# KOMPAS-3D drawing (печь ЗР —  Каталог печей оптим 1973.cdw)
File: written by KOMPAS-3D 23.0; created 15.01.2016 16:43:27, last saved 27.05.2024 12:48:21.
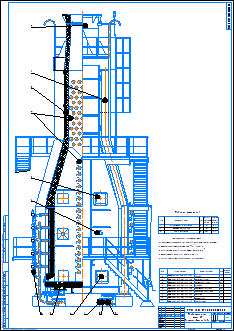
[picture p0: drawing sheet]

Sheet 1: A1, portrait

Document properties: Автор: pc; Наименование: Реактор гидроочистки установки Л-35-11/1000; Полное имя файла: G:\Учёба\Чертежи\Печь типа ЗР\Для публикации\печь ЗР —  Каталог печей оптим 1973.cdw

Title block, sheet 1: Наименование: Реактор гидроочистки / установки Л-35-11/1000.; scale: 1:20; Количество листов документа: 1; Форматы листов документа: A1; stored path: C:\Users\pc\Desktop\Работа\34 Элина Азаматовна\Реактор гидроочистки установки Л-24-5..cdw; designation, second copy: УТЭК.18.02.09.КП.09.00.000.СЗ-; Разработал: Низаева Э.А; Проверил: Пономарева Л.Ф

Referenced files: kzquor.frw
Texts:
  Материал-Предприятие
  Лит-Масса-Масштаб
  Normal
  K5LT32768_RGB_0_0_255_THICK_0.18
  POLYLINE_STYLE_0.18_RGB_0_0_255
  K5LT32769_RGB_0_0_0_THICK_0.18
  K5LT32770_RGB_255_127_0_SC_1_THICK_0.18
  POLYLINE_STYLE_0.18_RGB_0_0_0
  K5LT32772_RGB_0_0_0_SC_1_THICK_0.18
  K5LT_BASIC_RGB_0_0_255_THICK_0.6
  K5LT32771_RGB_0_0_0_THICK_0.18
  K5LT_THIN_RGB_0_0_0_THICK_0.18
  штрихпунктирная2_RGB_0_0_0_SC_1_THICK_0.2
  осевая2_RGB_0_0_0_SC_1_THICK_0.2
  МЕТАЛЛ_ANSI_ISO
  Стили документа
Dimensions and other numbers on the sheet: 1; 1:20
